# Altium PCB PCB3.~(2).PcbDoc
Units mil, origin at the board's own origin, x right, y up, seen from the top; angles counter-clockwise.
Board outline 5985.03 x 3125.03 mil, 2 copper layers (Top Layer, Bottom Layer); 86 components, 57 nets, 223 pads, 13 vias.
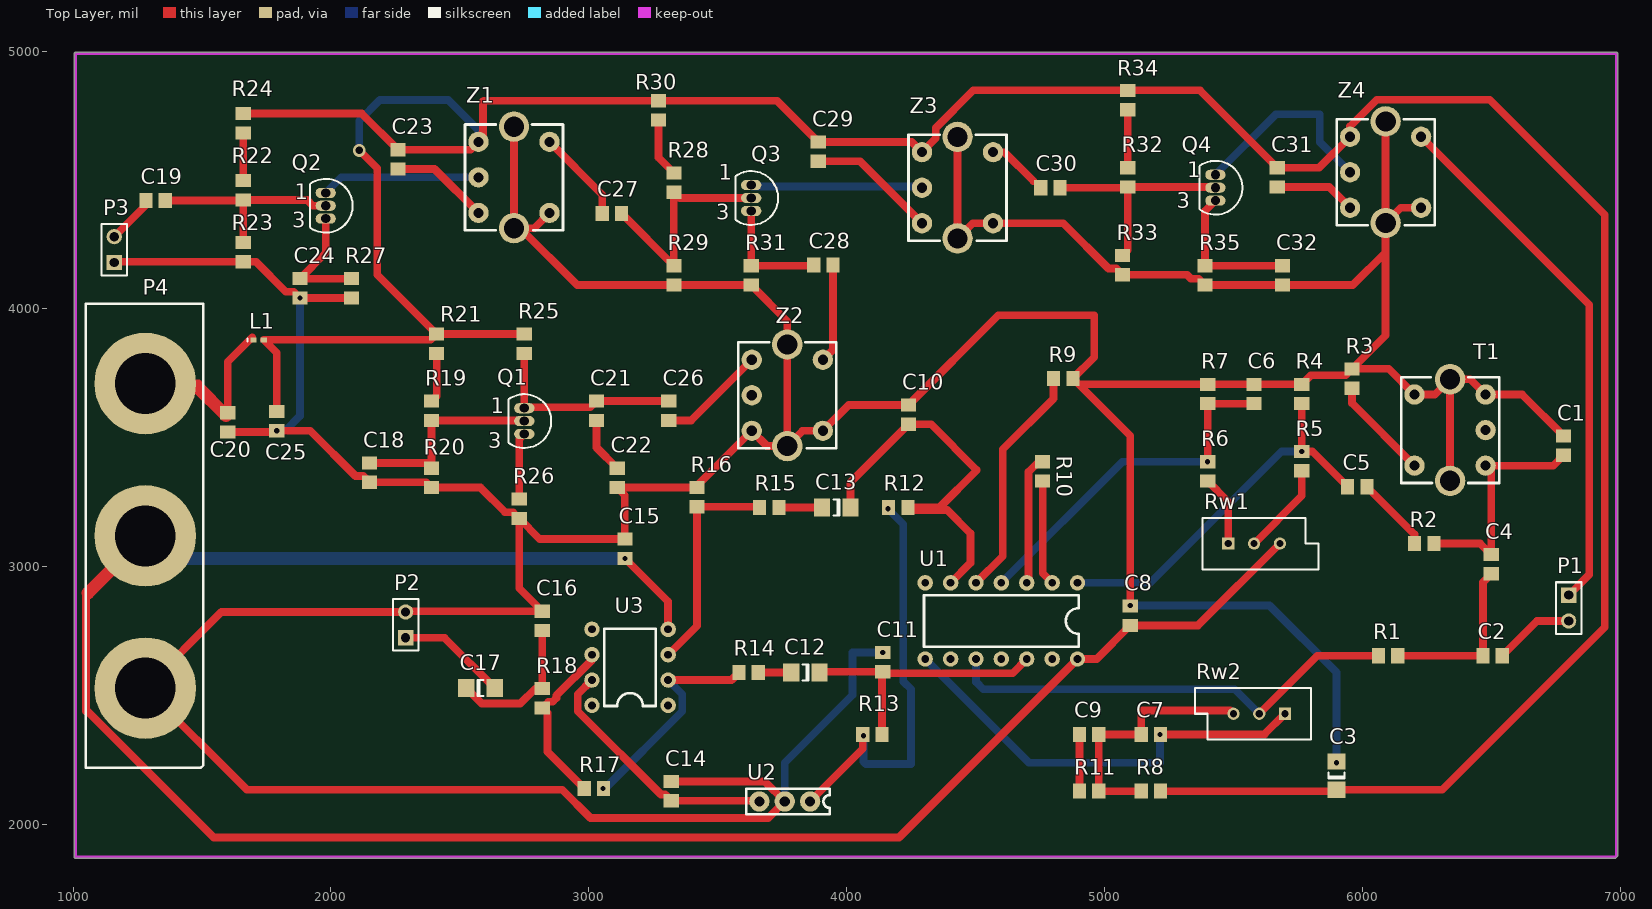
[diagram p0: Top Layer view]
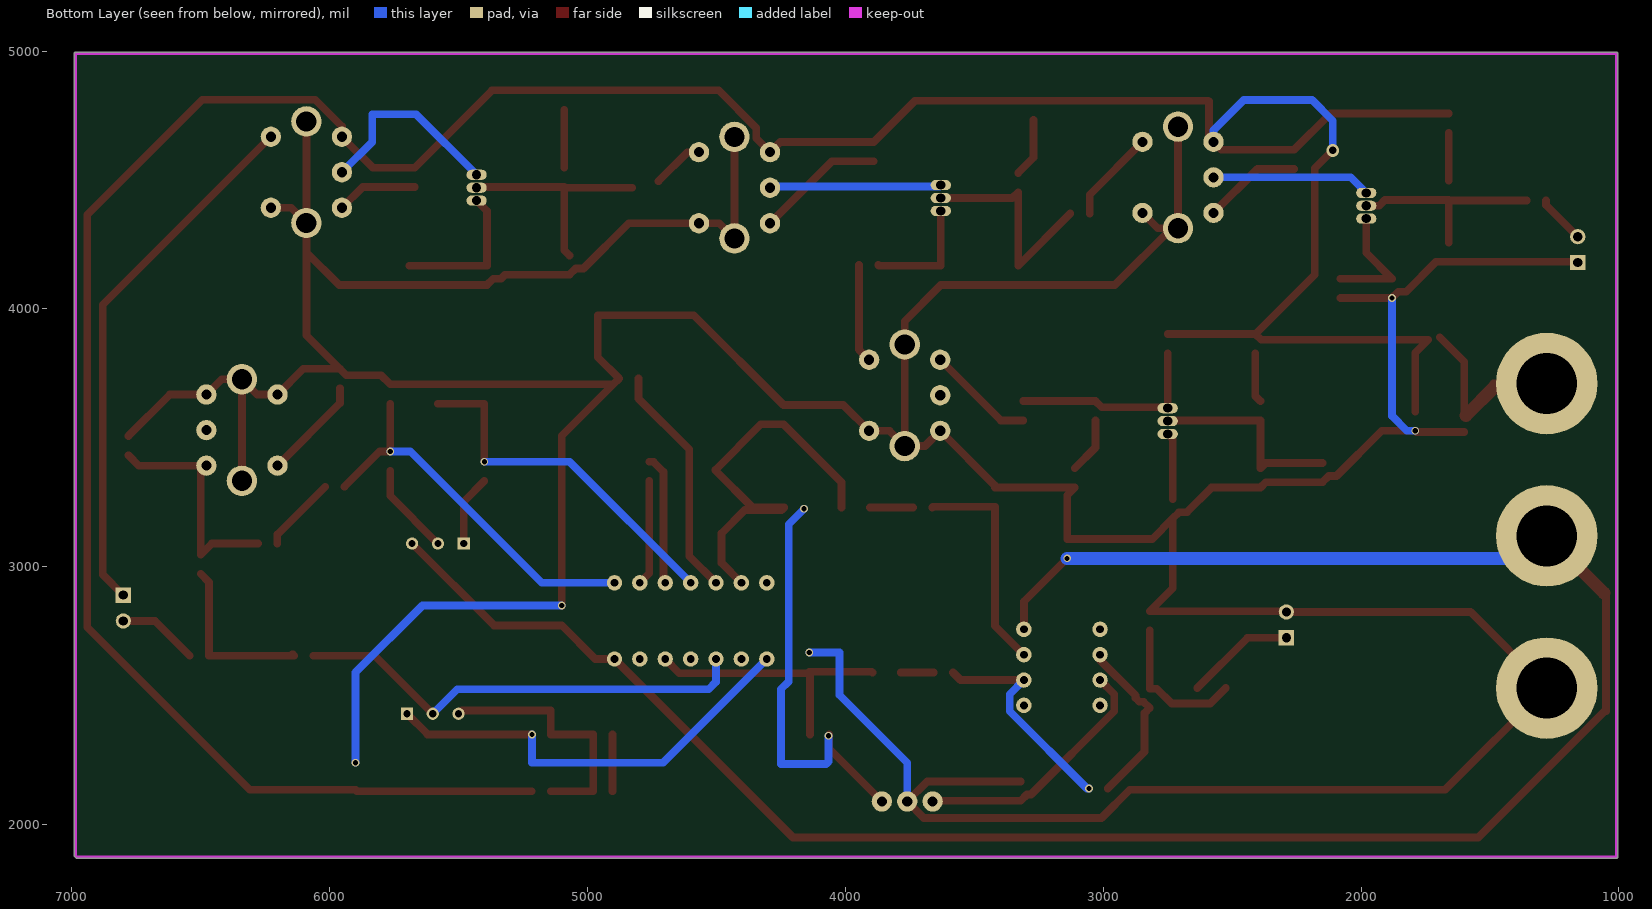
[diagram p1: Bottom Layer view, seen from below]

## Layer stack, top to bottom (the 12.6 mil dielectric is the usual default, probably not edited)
Top Layer: signal copper 1.4
Dielectric: dielectric 12.6, FR-4, Dk 4.8
Bottom Layer: signal copper 1.4

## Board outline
1010,1869.98 cw(c1010,1875) 1004.99,1875 1004.99,4990 cw(c1010,4990) 1010,4995.02 6985,4995.02 cw(c6985,4990) 6990.02,4990 6990.02,1880 cw(c6985,1880) 6988.53,1876.44 6988.55,1876.45 6983.55,1871.45 6983.56,1871.47 cw(c6980,1875) 6980,1869.98

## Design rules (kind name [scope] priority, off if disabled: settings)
Clearance [All] p1: gap=10
HoleSize [All] p1: absolutevalues=TRUE maxlimit=1000 minlimit=1 maxpercent=80.000 minpercent=20.000
HoleToHoleClearance [All] p1: gap=1 allowstackedmicrovias=TRUE
MinimumSolderMaskSliver [All] p1: minsoldermaskwidth=1
PolygonConnect [All] p1: connectstyle=Relief reliefconductorwidth=10 reliefentries=4 polygonreliefangle="90 Angle"
RoutingVias [All] p1: holewidth=28 width=50 viastyle="Through Hole" minholewidth=28 minwidth=50 maxholewidth=28 maxwidth=50
SilkscreenOverComponentPads [All] p1: minsilkscreentomaskgap=10
SolderMaskExpansion [All] p1: expansion=4
TestPointUsage [All] p1: valid=0 allowmultiple=FALSE
Testpoint [All] p1: side=15 testpointundercomponent=TRUE minsize=40 maxsize=100 preferedsize=60 minholesize=0 maxholesize=40 preferedholesize=32 testpointgrid=1 style=1023 order=0-112345678
Width [All] p1: maxlimit=100 minlimit=10 preferedwidth=10 toplayer_prefwidth=30 bottomlayer_prefwidth=30 minimp=50.000000 maximp=50.000000 favimp=50.000000
20 further rules are at their usual default settings.

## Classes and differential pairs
component class Sheet1: C1 C2 C3 C4 C5 C6 C7 C8 C9 C10 C11 C12 C13 C14 C15 C16 C17 P1 P2 R1 R2 R3 R4 R5 R6 R7 R8 R9 R10 R11 R12 R13 R14 R15 R16 R17 R18 Rw1 Rw2 T1 U1 U2 U3
component class Sheet2: C18 C19 C20 C21 C22 C23 C24 C25 C26 C27 C28 C29 C30 C31 C32 L1 P3 P4 Q1 Q2 Q3 Q4 R19 R20 R21 R22 R23 R24 R25 R26 R27 R28 R29 R30 R31 R32 R33 R34 R35 Z1 Z2 Z3 Z4

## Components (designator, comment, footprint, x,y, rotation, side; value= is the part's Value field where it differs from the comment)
C1 "Cap" 2012[0805] 6780,3470 r270 top
C2 "Cap" 2012[0805] 6505,2655 r180 top
C3 "Cap Pol1" C1206 5900,2190 r90 top
C4 "Cap" 2012[0805] 6500,3010 r270 top
C5 "Cap" 2012[0805] 5980,3310 r180 top
C6 "Cap" 2012[0805] 5580,3670 r270 top
C7 "Cap" 2012[0805] 5180,2350 r180 top
C8 "Cap" 2012[0805] 5100,2810 r270 top
C9 "Cap" 2012[0805] 4940,2350 r180 top
C10 "Cap" 2012[0805] 4240,3590 r270 top
C11 "Cap" 2012[0805] 4140,2630 r270 top
C12 "Cap Pol1" C1206 3840,2590 r180 top
C13 "Cap Pol1" C1206 3960,3230 r180 top
C14 "Cap" 2012[0805] 3320,2130 r270 top
C15 "Cap" 2012[0805] 3140,3070 r270 top
C16 "Cap" 2012[0805] 2820,2790 r270 top
C17 "Cap Pol1" C1206 2580,2530 r0 top
C18 "Cap" 2012[0805] 2150,3365 r270 top
C19 "Cap" 2012[0805] 1320,4420 r0 top
C20 "Cap" 2012[0805] 1600,3560 r90 top
C21 "Cap" 2012[0805] 3030,3605 r270 top
C22 "Cap" 2012[0805] 3110,3345 r270 top
C23 "Cap" 2012[0805] 2260,4580 r270 top
C24 "Cap" 2012[0805] 1880,4080 r90 top
C25 "Cap" 2012[0805] 1790,3565 r90 top
C26 "Cap" 2012[0805] 3310,3605 r90 top
C27 "Cap" 2012[0805] 3090,4370 r0 top
C28 "Cap" 2012[0805] 3910,4170 r0 top
C29 "Cap" 2012[0805] 3890,4610 r270 top
C30 "Cap" 2012[0805] 4790,4470 r0 top
C31 "Cap" 2012[0805] 5670,4510 r270 top
C32 "Cap" 2012[0805] 5690,4130 r90 top
L1 "Inductor" 0402-A 1720,3880 r0 top
P1 "Header 2" HDR1X2 6800,2890 r270 top
P2 "Header 2" HDR1X2 2290,2725 r90 top
P3 "Header 2" HDR1X2 1160,4180 r90 top
P4 "Header 3" shuru 1280,3120 r90 top
Q1 "NPN" TO-226 2750,3565 r180 top
Q2 "NPN" TO-226 1980,4400 r180 top
Q3 "NPN" TO-226 3630,4430 r180 top
Q4 "NPN" TO-226 5430,4470 r180 top
R1 "Res1" 2012[0805] 6100,2655 r180 top
R2 "Res1" 2012[0805] 6240,3090 r180 top
R3 "Res1" 2012[0805] 5960,3730 r270 top
R4 "Res1" 2012[0805] 5765,3670 r270 top
R5 "Res1" 2012[0805] 5765,3410 r270 top
R6 "Res1" 2012[0805] 5400,3370 r270 top
R7 "Res1" 2012[0805] 5400,3670 r270 top
R8 "Res1" 2012[0805] 5180,2130 r180 top
R9 "Res1" 2012[0805] 4840,3730 r180 top
R10 "Res1" 2012[0805] 4760,3370 r270 top
R11 "Res1" 2012[0805] 4940,2130 r180 top
R12 "Res1" 2012[0805] 4200,3230 r180 top
R13 "Res1" 2012[0805] 4100,2350 r180 top
R14 "Res1" 2012[0805] 3620,2590 r180 top
R15 "Res1" 2012[0805] 3700,3230 r180 top
R16 "Res1" 2012[0805] 3420,3270 r270 top
R17 "Res1" 2012[0805] 3020,2140 r180 top
R18 "Res1" 2012[0805] 2820,2490 r270 top
R19 "Res1" 2012[0805] 2390,3605 r90 top
R20 "Res1" 2012[0805] 2390,3345 r90 top
R21 "Res Adj1" 2012[0805] 2410,3865 r270 top
R22 "Res1" 2012[0805] 1660,4460 r90 top
R23 "Res1" 2012[0805] 1660,4220 r90 top
R24 "Res Adj1" 2012[0805] 1660,4720 r270 top
R25 "Res1" 2012[0805] 2750,3865 r90 top
R26 "Res1" 2012[0805] 2730,3225 r90 top
R27 "Res1" 2012[0805] 2080,4080 r90 top
R28 "Res1" 2012[0805] 3330,4490 r90 top
R29 "Res1" 2012[0805] 3330,4130 r90 top
R30 "Res Adj1" 2012[0805] 3270,4770 r270 top
R31 "Res1" 2012[0805] 3630,4130 r90 top
R32 "Res1" 2012[0805] 5090,4510 r90 top
R33 "Res1" 2012[0805] 5070,4170 r90 top
R34 "Res Adj1" 2012[0805] 5090,4810 r270 top
R35 "Res1" 2012[0805] 5390,4130 r90 top
Rw1 "RPot" VR5 5580,3090 r0 top
Rw2 "RPot" VR5 5600,2430 r180 top
T1 "zhongzhou" ZHONGZHOU 6340,3530 r180 top
U1 "MC1496" MC1496 4600,2790 r180 top
U2 "LM7808" LM7808 3760,2090 r180 top
U3 "LM741" LM741 3160,2610 r180 top
Z1 "zhongzhou1" ZHONGZHOU 2710,4510 r0 top
Z2 "zhongzhou2" ZHONGZHOU 3770,3665 r0 top
Z3 "zhongzhou3" ZHONGZHOU 4430,4470 r0 top
Z4 "zhongzhou4" ZHONGZHOU 6090,4530 r0 top

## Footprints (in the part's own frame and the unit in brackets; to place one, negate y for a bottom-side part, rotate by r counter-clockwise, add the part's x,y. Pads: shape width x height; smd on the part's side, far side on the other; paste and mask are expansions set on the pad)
0402-A [mm] "Chip Inductor; Body 1 x 0.5 mm (LxW typ)"
  rect 0.6x0.5 smd: 1(-0.5,0) 2(0.5,0)
  silkscreen extent -1.1,-0.15 -1.1,0.15
2012[0805] [mm] "Chip Resistor; Body 2.0 x 1.3 mm (LxW typ)"
  rect 1.3x1.5 smd: 1(-0.95,0) 2(0.95,0)
C1206 [mm] "Chip Capacitor; Body 3.2 x 1.6 mm (LxW typ)"
  rect 1.6x1.8 smd: 1(-1.4,0) 2(1.4,0)
  silkscreen extent -0.3,-0.8 0.3,0.8
HDR1X2 [mm] "Connector; Header; 2 Position"
  rect 1.5x1.5 hole 0.9: 1(0,0)
  round 1.5 hole 0.9: 2(2.54,0)
  silkscreen extent -1.27,-1.27 3.81,1.27
LM741 [mil]
  round 60 hole 30: 1(-147.64,147.64) 2(-147.64,49.21) 3(-147.64,-49.21) 4(-147.64,-147.64) 5(147.64,-147.64) 6(147.64,-49.21) 7(147.64,49.21) 8(147.64,147.64)
  silkscreen extent -100,-150 100,150
LM7808 [mm]
  round 2 hole 1: 1(-2.5,0) 2(0,0) 3(2.5,0)
  silkscreen extent -4.44,-1.27 3.81,1.27
MC1496 [mil]
  round 60 hole 30: 1(-295.28,-147.64) 2(-196.85,-147.64) 3(-98.43,-147.64) 4(0,-147.64) 5(98.43,-147.64) 6(196.85,-147.64) 7(295.28,-147.64) 8(295.28,147.64) 9(196.85,147.64) 10(98.43,147.64) 11(0,147.64) 12(-98.43,147.64) 13(-196.85,147.64) 14(-295.28,147.64)
  silkscreen extent -300,-100 300,100
shuru [mm]
  round 10 hole 6: 1(-15,0) 2(0,0) 3(15,0)
  silkscreen extent -22.86,-5.72 22.86,5.84
TO-226 [mm] "TO, Flat Index; 3 In-Line, Axial Leads; Body Dia. 4.8mm; Leads 0.55 x 0.51 mm (max)"
  oval 2x1 hole 0.9: 1(0,-1.27) 2(0,0) 3(0,1.27)
  silkscreen extent -2.65,-2.65 1.55,2.65
VR5 [mm] "Potentiometer; 3 Leads"
  rect 1.2x1.2 hole 0.7: 1(-2.54,0)
  round 1.2 hole 0.7: 2(0,0) 3(2.54,0)
  silkscreen extent -5.08,-2.54 6.35,2.54
ZHONGZHOU [mm]
  round 2 hole 1: 1(-3.5,3.5) 2(-3.5,0) 3(-3.5,-3.5) 4(3.5,-3.5) 5(3.5,3.5)
  round 3 hole 2: 6(0,5) 7(0,-5)
  silkscreen extent -4.83,-5.21 4.83,5.21

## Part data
C1 C2 C4 C5 C6 C7 C8 C9 C10 C11 C14 C15 C16 C18 C19 C20 C21 C22 C23 C24 C25 C26 C27 C28 C29 C30 C31 C32: "Capacitor"
C3 C12 C13 C17: "Polarized Capacitor (Radial)"
P1 P2 P3: "Header, 2-Pin"
P4: "Header, 3-Pin"
Q1 Q2 Q3 Q4: "NPN Bipolar Transistor"
R1 R2 R3 R4 R5 R6 R7 R8 R9 R10 R11 R12 R13 R14 R15 R16 R17 R18 R19 R20 R22 R23 R25 R26 R27 R28 R29 R31 R32 R33 R35: "Resistor"
R21 R24 R30 R34: "Variable Resistor"
Rw1 Rw2: "Potentiometer"
Z2: library part zhongzhou4
Z3: library part zhongzhou2
Z4: library part zhongzhou3

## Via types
v1: diameter 30, hole 20, Top Layer to Bottom Layer, 12 vias
v2: diameter 50, hole 28, Top Layer to Bottom Layer, 1 vias

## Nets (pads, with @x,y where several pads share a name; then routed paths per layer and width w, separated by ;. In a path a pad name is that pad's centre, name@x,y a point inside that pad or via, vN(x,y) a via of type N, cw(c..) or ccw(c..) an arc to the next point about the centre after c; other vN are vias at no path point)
+12V: C3.1 C23.1 C25.2 C29.1 C31.1 L1.2 R8.1 R21.1 R24.1 R25.2 R30.1 R34.1 Z1.1 Z3.1 Z4.1 | length 12589.8
  Top Layer w30: R24.1 2120,4757.4 C23.1 2541.81,4617.4 Z1.1 2590,4665.59 2590,4805 2592.4,4807.4 3730,4807.4 C29.1 4252.6,4647.4 Z3.1 4345.94,4661.54 4345.94,4701.67 4491.68,4847.4 R34.1 5370,4847.4 C31.1 5831.81,4547.4 Z4.1 5952.2,4707.93 6055.18,4810.91 6494.09,4810.91 6940,4365 6940,2765 6309.88,2134.88 C3.1 5895.12,2130 R8.1 ; C25.2 1790,3829.69 L1.2 2387.6,3880 R21.1 ; v2(2110,4615) 2180,4545 2180,4132.4 R21.1 ; R25.2 R21.1
  Bottom Layer w30: v2(2110,4615) 2110,4730 2190,4810 2455,4810 2572.2,4692.8 Z1.1
-8V: C8.2 C15.2 P4.2 Rw1.3 U1.14 U3.4 | length 8310.9
  Top Layer w30: 1050,2439.41 1050,2900 ; 1058.15,2437.55 1545.7,1950 4202.91,1950 U1.14 4969.76,2642.36 C8.2 5362.6,2772.6 Rw1.3 ; v1(3140,3032.6) 3307.64,2864.96 U3.4
  Top Layer w50: 1058.15,2898.15 P4.2
  Bottom Layer w30: P4.2 P4.2@1367.4,3032.6
  Bottom Layer w50: P4.2@1367.4,3032.6 v1(3140,3032.6)
GND: C1.1 C3.2 C6.1 C8.1 C10.1 C11.1 C14.1 C15.1 C16.1 C18.2 C20.1 C22.2 C24.1 C25.1 C32.1 P2.2 P3.1 P4.1 R3.1 R4.1 R7.1 R9.1 R16.1 R20.1 R23.1 R26.1 R27.1 R29.1 R31.1 R33.1 R35.1 T1.3 T1.4 T1.6 T1.7 U2.2 Z1.4 Z1.6 Z1.7 Z2.3 Z2.4 Z2.6 Z2.7 Z3.4 Z3.6 Z3.7 Z4.4 Z4.6 Z4.7 | length 22308
  Top Layer w30: P3.1 1162.6,4182.6 R23.1 1709.69,4182.6 1825.47,4066.81 1855.79,4066.81 v1(1880,4042.6) R27.1 ; C20.1 1785,3522.6 v1(1790,3527.6) 1919.69,3527.6 2095.47,3351.81 2125.79,3351.81 C18.2 2370,3327.6 R20.1 2579.69,3307.6 2675.47,3211.81 2705.79,3211.81 R26.1 ; Z1.6 Z1.7 Z1.7@2735,4313.15 ; Z1.4 2788.74,4313.15 Z1.7@2735,4313.15 ; C14.1 3682.6,2167.4 U2.2 3695.63,2025.63 3006.49,2025.63 2897.12,2135 1674.45,2135 P4.1 1575.55,2825 P2.2 2292.4,2827.4 C16.1 2730,2917.4 R26.1 ; Z3.6 Z3.7 4489.05,4332.2 Z3.4 4840.08,4332.2 5015.47,4156.81 5045.79,4156.81 R33.1 5319.69,4132.6 5335.47,4116.81 5365.79,4116.81 R35.1 C32.1 5962.6,4092.6 6090,4220 ; C8.1 5100,3507.4 R9.1@4900,3707.4 ; Z4.6 Z4.7 ; Z4.4 6149.05,4392.2 Z4.7 ; T1.6 T1.7 ; C1.1 6619.61,3667.8 T1.3 6418.74,3726.85 T1.7 ; R26.1 2810.2,3107.4 C15.1 3140,3277.6 3110.2,3307.4 R16.1 3420,3315 Z2.3 3691.26,3468.15 Z2.7 ; Z1.7@2735,4313.15 2955.55,4092.6 R29.1 R31.1 3770,3952.6 Z2.6 Z2.7 ; Z2.7 3829.05,3527.2 Z2.4 4007.99,3627.4 C10.1 4587.6,3975 4960,3975 4960,3812.6 R9.1 R9.1@4900,3707.4 ; R9.1@4900,3707.4 R7.1 C6.1 R4.1 5800.79,3743.19 5935.79,3743.19 R3.1 ; R3.1 6090,3897.4 6090,4220 ; R3.1 6102.6,3767.4 T1.4 6280.95,3667.8 T1.7 ; 6090,4220 Z4.7
  Bottom Layer w30: v1(1790,3527.6) 1822.6,3527.6 1880,3585 v1(1880,4042.6) ; U2.2 3760,2240 4022.4,2502.4 4022.4,2667.4 v1(4140,2667.4) ; v1(5100,2850) 5640,2850 5900,2590 v1(5900,2240)
NetC1_2: C1.2 C4.1 R2.1 T1.1 | length 913.2
  Top Layer w30: R2.1 6457.4,3090 C4.1 6500,3370 T1.1 6739.61,3392.2 C1.2
NetC2_1: C2.1 P1.2 | length 313.5
  Top Layer w30: C2.1 6677.4,2790 P1.2
NetC2_2: C2.2 C4.2 R1.1 | length 665.9
  Top Layer w30: R1.1 6142.4,2660 R1.1@6145,2660 ; R1.1@6142.4,2655 C2.2 6467.6,2940.2 C4.2
NetC5_1: C5.1 R2.2 | length 296.7
  Top Layer w30: C5.1 6202.6,3124.8 R2.2
NetC5_2: C5.2 R4.2 R5.1 U1.1 | length 1500.6
  Top Layer w30: R4.2 v1(5765,3447.4) 5805.2,3447.4 C5.2
  Bottom Layer w30: U1.1 5177.64,2937.64 5687.4,3447.4 v1(5765,3447.4)
NetC6_2: C6.2 R6.1 R7.2 U1.4 | length 1399.8
  Top Layer w30: v1(5400,3407.4) R7.2 C6.2
  Bottom Layer w30: U1.4 5069.76,3407.4 v1(5400,3407.4)
NetC7_1: C7.1 Rw2.1 U1.8 | length 1702.7
  Top Layer w30: C7.1 5620,2350 Rw2.1
  Bottom Layer w30: U1.8 4707.09,2240 5215,2240 v1(5215,2350)
NetC7_2: C7.2 C9.1 R8.2 R11.1 Rw2.3 | length 1005.3
  Top Layer w30: R8.2 R11.1 C9.1 C7.2 5142.6,2442.4 5487.6,2442.4 Rw2.3
NetC9_2: C9.2 R11.2 | length 220
  Top Layer w30: R11.2 C9.2
NetC10_2: C10.2 C13.1 R12.1 U1.6 | length 1590.2
  Top Layer w30: C13.1 4015.12,3327.72 C10.2 4327.4,3552.6 4505,3375 4360,3230 R12.1 4247.4,3220 4390,3220 4480,3130 4480,3014.49 U1.6
NetC11_2: C11.2 C12.1 R13.1 U1.12 | length 1073
  Top Layer w30: C12.1 3897.72,2592.6 C11.2 ; R13.1 4137.4,2590 C11.2 ; U1.12 4643.43,2587.36 4145.24,2587.36 C11.2
NetC12_2: C12.2 R14.1 | length 127.5
  Top Layer w30: R14.1 C12.2
NetC13_2: C13.2 R15.1 | length 167.5
  Top Layer w30: R15.1 C13.2
NetC14_2: C14.2 U2.3 U3.7 | length 993
  Top Layer w30: U3.7 2957.36,2505.79 2957.36,2439.57 3280.12,2116.81 3295.79,2116.81 C14.2 3658.98,2092.6 U2.3
NetC16_2: C16.2 C17.1 R18.1 | length 569.3
  Top Layer w30: C17.1 2585.32,2469.57 2734.57,2469.57 2792.4,2527.4 R18.1 C16.2
NetC17_2: C17.2 P2.1 | length 425.9
  Top Layer w30: P2.1 2440.12,2725 C17.2
NetC18_1: C18.1 Q1.2 R19.1 R20.2 | length 794.6
  Top Layer w30: C18.1 2370,3402.4 R20.2 R19.1 2747.4,3567.6 Q1.2
NetC19_1: C19.1 P3.2 | length 208.2
  Top Layer w10: P3.2 P3.2@1160,4297.4
  Top Layer w30: P3.2 1282.6,4402.6 C19.1
NetC19_2: C19.2 Q2.2 R22.1 R23.2 | length 798.2
  Top Layer w30: C19.2 1657.4,4420 R22.1 ; R23.2 R22.1 ; Q2.2 1929.84,4400 1907.24,4422.6 R22.1
NetC20_2: C20.2 L1.1 P4.3 | length 698.8
  Top Layer w30: P4.3 1486.85,3710.55 ; C20.2 1600,3795 1695,3890
  Top Layer w50: 1480,3700 C20.2@1593.15,3586.85
NetC21_1: C21.1 C26.2 Q1.1 R25.1 | length 783.9
  Top Layer w30: R25.1 Q1.1 2753.19,3618.19 3005.79,3618.19 C21.1 C26.2
NetC21_2: C21.2 C22.1 | length 218.3
  Top Layer w30: C21.2 3030,3462.4 C22.1
NetC23_2: C23.2 Z1.3 | length 382.8
  Top Layer w30: C23.2 2401.81,4542.6 Z1.3
NetC24_2: C24.2 Q2.3 R27.2 | length 474
  Top Layer w30: Q2.3 1980,4217.4 C24.2 R27.2
NetC26_1: C26.1 Z2.1 | length 419.6
  Top Layer w30: C26.1 3397.01,3567.6 Z2.1
NetC27_1: C27.1 Z1.5 | length 362.6
  Top Layer w30: Z1.5 3052.6,4442.99 C27.1
NetC27_2: C27.2 Q3.2 R28.1 R29.2 | length 881.1
  Top Layer w30: C27.2 R29.2 R28.1 3352.6,4430 Q3.2
NetC28_1: C28.1 Q3.3 R31.2 | length 456.3
  Top Layer w30: Q3.3 R31.2 3870,4167.4 C28.1
NetC28_2: C28.2 Z2.5 | length 383.6
  Top Layer w30: Z2.5 3947.4,3842.4 C28.2
NetC29_2: C29.2 Z3.3 | length 501.8
  Top Layer w30: C29.2 4051.81,4572.6 Z3.3
NetC30_1: C30.1 Z3.5 | length 203.9
  Top Layer w30: Z3.5 4612.2,4607.8 4725,4495
NetC30_2: C30.2 Q4.2 R32.1 R33.2 | length 878.2
  Top Layer w30: C30.2 5087.4,4470 R32.1 ; R33.2 5090,4227.4 R32.1 ; Q4.2 5427.4,4472.6 R32.1
NetC31_2: C31.2 Z4.3 | length 315.5
  Top Layer w30: C31.2 5871.81,4472.6 Z4.3
NetC32_2: C32.2 Q4.3 R35.2 | length 569.2
  Top Layer w30: Q4.3 5390,4380 R35.2 C32.2
NetQ1_3: Q1.3 R26.2 | length 260.9
  Top Layer w30: R26.2 2730,3495 Q1.3
NetQ2_1: Q2.1 Z1.2 | length 617.1
  Bottom Layer w30: Q2.1 2040,4510 Z1.2
NetQ3_1: Q3.1 Z3.2 | length 666.3
  Bottom Layer w30: Q3.1 3635.32,4474.69 4287.52,4474.69 Z3.2
NetQ4_1: Q4.1 Z4.2 | length 775.9
  Bottom Layer w30: Q4.1 5665,4755 5835,4755 5835,4647.2 Z4.2
NetR1_2: R1.2 Rw2.2 U1.10 | length 1794.3
  Top Layer w30: Rw2.2 5825,2655 R1.2
  Bottom Layer w30: U1.10 4501.57,2553.43 4530,2525 5505,2525 Rw2.2
NetR3_2: R3.2 T1.5 | length 400.7
  Top Layer w30: R3.2 5960,3634.41 T1.5
NetR5_2: R5.2 Rw1.2 | length 359.2
  Top Layer w30: Rw1.2 5765,3275 R5.2
NetR6_2: R6.2 Rw1.1 | length 275.7
  Top Layer w30: R6.2 5480,3252.6 Rw1.1
NetR9_2: R9.2 U1.5 | length 917.1
  Top Layer w30: U1.5 4605,3041.06 4605,3455 4802.6,3652.6 R9.2
NetR10_1: R10.1 U1.3 | length 504.4
  Top Layer w30: U1.3 4705.47,2944.68 4705.47,3368.54 4744.33,3407.4 R10.1
NetR10_2: R10.2 U1.2 | length 410.2
  Top Layer w30: R10.2 4760,2974.49 U1.2
NetR12_2: R12.2 R13.2 U2.1 | length 1661
  Top Layer w30: U2.1 4062.6,2294.17 R13.2
  Bottom Layer w30: v1(4065,2345) 4065,2245 4075,2235 4250,2235 4250,2525 4220,2555 4220,3165 v1(4160,3225)
NetR14_2: R14.2 R17.1 U3.2 | length 862.8
  Top Layer w30: U3.2 3553.39,2560.79 R14.2
  Bottom Layer w30: v1(3055,2140) 3063.06,2140 3362.64,2439.58 3362.64,2505.79 U3.2
NetR15_2: R15.2 R16.2 U3.3 | length 863.6
  Top Layer w30: U3.3 3420,2771.57 R16.2 3660,3232.6 R15.2
NetR17_2: R17.2 R18.2 U3.6 | length 675.4
  Top Layer w30: R17.2 2840,2282.6 2840,2432.6 R18.2 2844.21,2476.81 2859.88,2476.81 2874.53,2491.46 2874.53,2500.74 3012.36,2638.57 U3.6
NetR19_2: R19.2 R21.2 | length 193.5
  Top Layer w30: R19.2 2410,3662.4 R21.2
NetR22_2: R22.2 R24.2 | length 185.2
  Top Layer w30: R22.2 R24.2
NetR28_2: R28.2 R30.2 | length 230
  Top Layer w30: R30.2 3270,4587.4 R28.2
NetR32_2: R32.2 R34.2 | length 225.2
  Top Layer w30: R32.2 R34.2
ZHONGFANG: P1.1 Z4.5 | length 2081.1
  Top Layer w30: Z4.5 6880,4015.59 6880,2970 P1.1
pads on no net: T1.2 U1.7 U1.9 U1.11 U1.13 U3.1 U3.5 U3.8 Z2.2

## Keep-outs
Keep-Out Layer:
  lines w10: 1010,1875 6980,1875 6985,1880 6985,4990 1010,4990 1010,1875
